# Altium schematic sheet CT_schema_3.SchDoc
size 176 x 147 mm
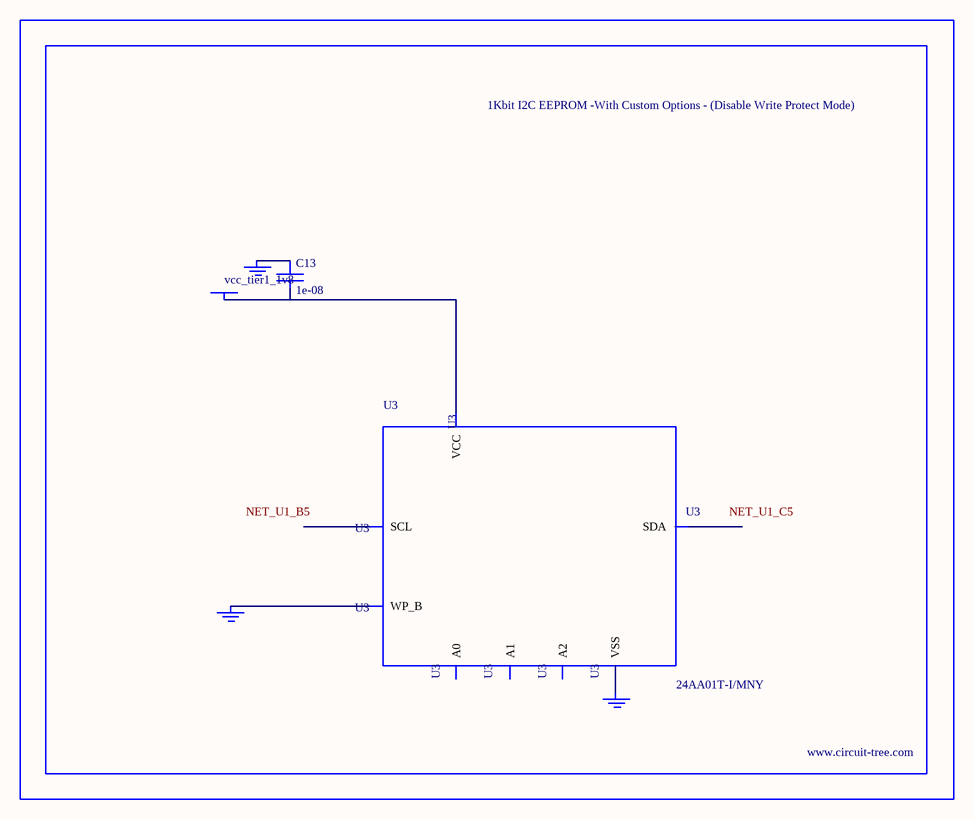
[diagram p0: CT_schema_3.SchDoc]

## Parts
BORDER2  (no value)
C13  1e-08  [C0402]
GND_INSTANCE_2_0  (no value)
GND_INSTANCE_2_1  (no value)
GND_INSTANCE_2_2  (no value)
POWER_INSTANCE_2_0  vcc_tier1_1v8
U3  24AA01T-I/MNY  [TDFN-8/6MM]

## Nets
NetC13_1: C13.1 GND_INSTANCE_2_1.0(GND)
NetC13_2: C13.2 POWER_INSTANCE_2_0.0(PWR) U3.8(VCC)
NetGND_INSTANCE_2_0_0: GND_INSTANCE_2_0.0(GND) U3.7(WP_B)
NetGND_INSTANCE_2_2_0: GND_INSTANCE_2_2.0(GND) U3.4(VSS)

Not connected (* = marked no-connect by the designer): U3 1(A0) 2(A1) 3(A2) 5(SDA) 6(SCL)

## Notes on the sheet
- Labels drawn without touching a wire or pin: NET_U1_B5, NET_U1_C5

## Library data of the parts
BORDER2 = BORDER_PAGE2
C13 = C0402C103K3RAC
GND_INSTANCE_2_0-GND_INSTANCE_2_2 = GND
POWER_INSTANCE_2_0 = PWR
